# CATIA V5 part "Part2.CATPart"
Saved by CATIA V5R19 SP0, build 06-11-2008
Part number: Part2
Bounding box of the stored display mesh (mm): x -53.402 to 71.586, y -25.205 to 55.128, z 30 to 30
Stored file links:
  C:\Documents and Settings\Jan Svoboda\Plocha\CATIA-help\Test_public\Part2.CATPart
  C:\Documents and Settings\Jan Svoboda\Plocha\CATIA-help\Test_public\Product1.CATProduct
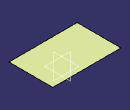
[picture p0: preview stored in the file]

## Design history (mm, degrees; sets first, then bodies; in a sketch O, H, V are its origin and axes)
Set1
  DatumSurface1: linked copy from another document
Body1 (main body)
